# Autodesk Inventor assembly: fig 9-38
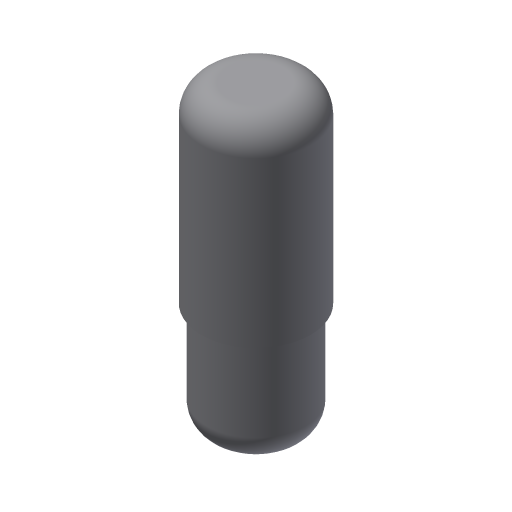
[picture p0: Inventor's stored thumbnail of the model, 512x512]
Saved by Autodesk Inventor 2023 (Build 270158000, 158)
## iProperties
Created: 2013-07
Part Number: fig 9-38
Document SubType Name: Assembly
Designer: CADCIM
Author: CADCIM
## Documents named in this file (3)
- D:\PROJECTS\Project 2022\Autodesk Inventor For Professional 2023\RESOURCES INVENTOR 2023\RESOURCES INVENTOR 2023\Inventor_2023_Part\Inventor_2023_Part\c09_Inv_2023_prt\fig 9-39.iam
- D:\PROJECTS\Project 2022\Autodesk Inventor For Professional 2023\RESOURCES INVENTOR 2023\RESOURCES INVENTOR 2023\Inventor_2023_Part\Inventor_2023_Part\c09_Inv_2023_prt\10.ipt
- D:\PROJECTS\Project 2022\Autodesk Inventor For Professional 2023\RESOURCES INVENTOR 2023\RESOURCES INVENTOR 2023\Inventor_2023_Part\Inventor_2023_Part\c09_Inv_2023_prt\11.ipt
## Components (2 placed, 2 different names)
1. 10:1 — Rigid:1
2. 11:1 — Rigid:1
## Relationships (1: WeldJoint 1)
- Rigid:1 [WeldJoint]: 10:1 ↔ 11:1
